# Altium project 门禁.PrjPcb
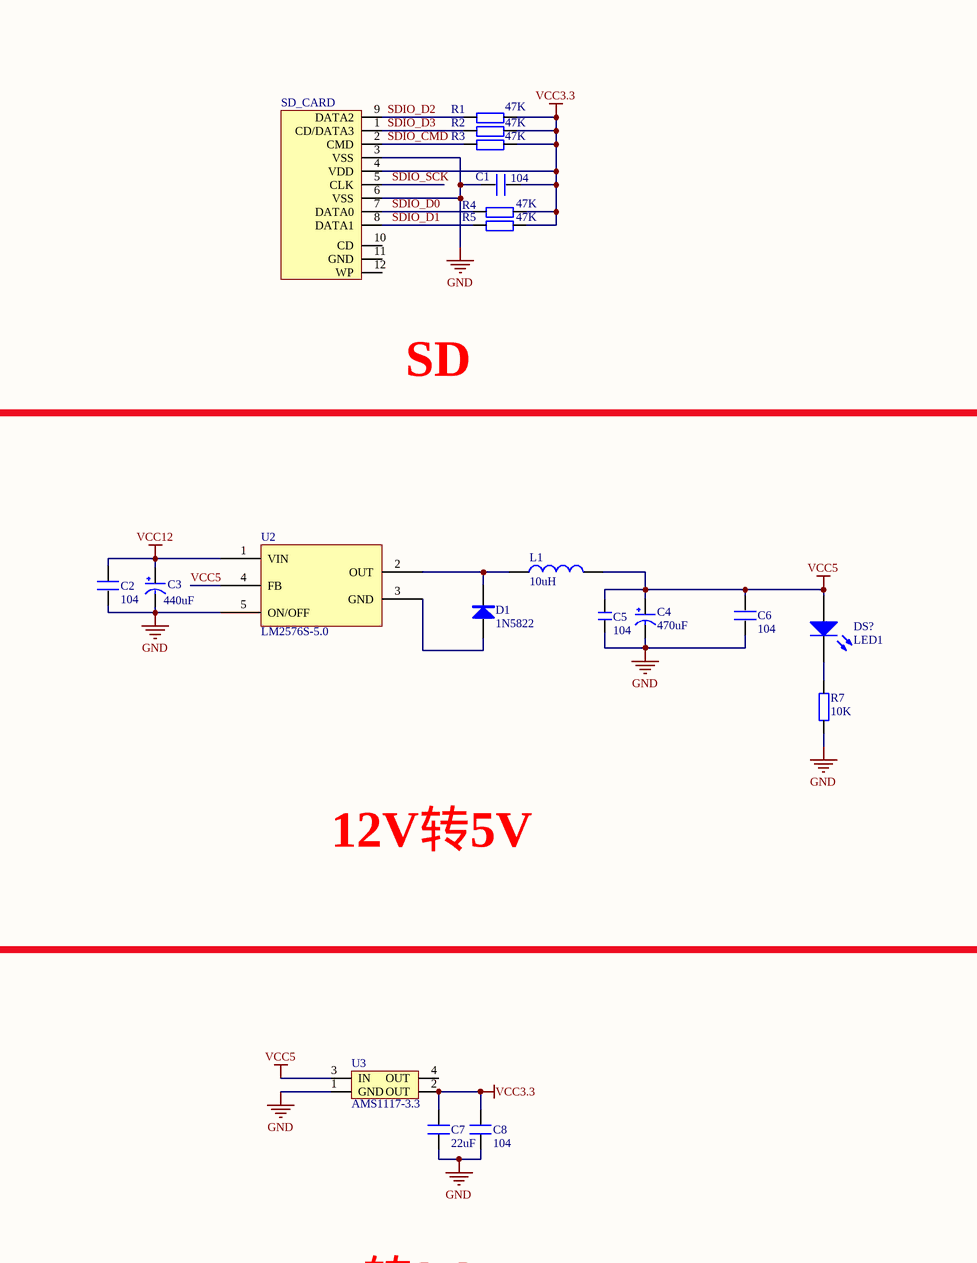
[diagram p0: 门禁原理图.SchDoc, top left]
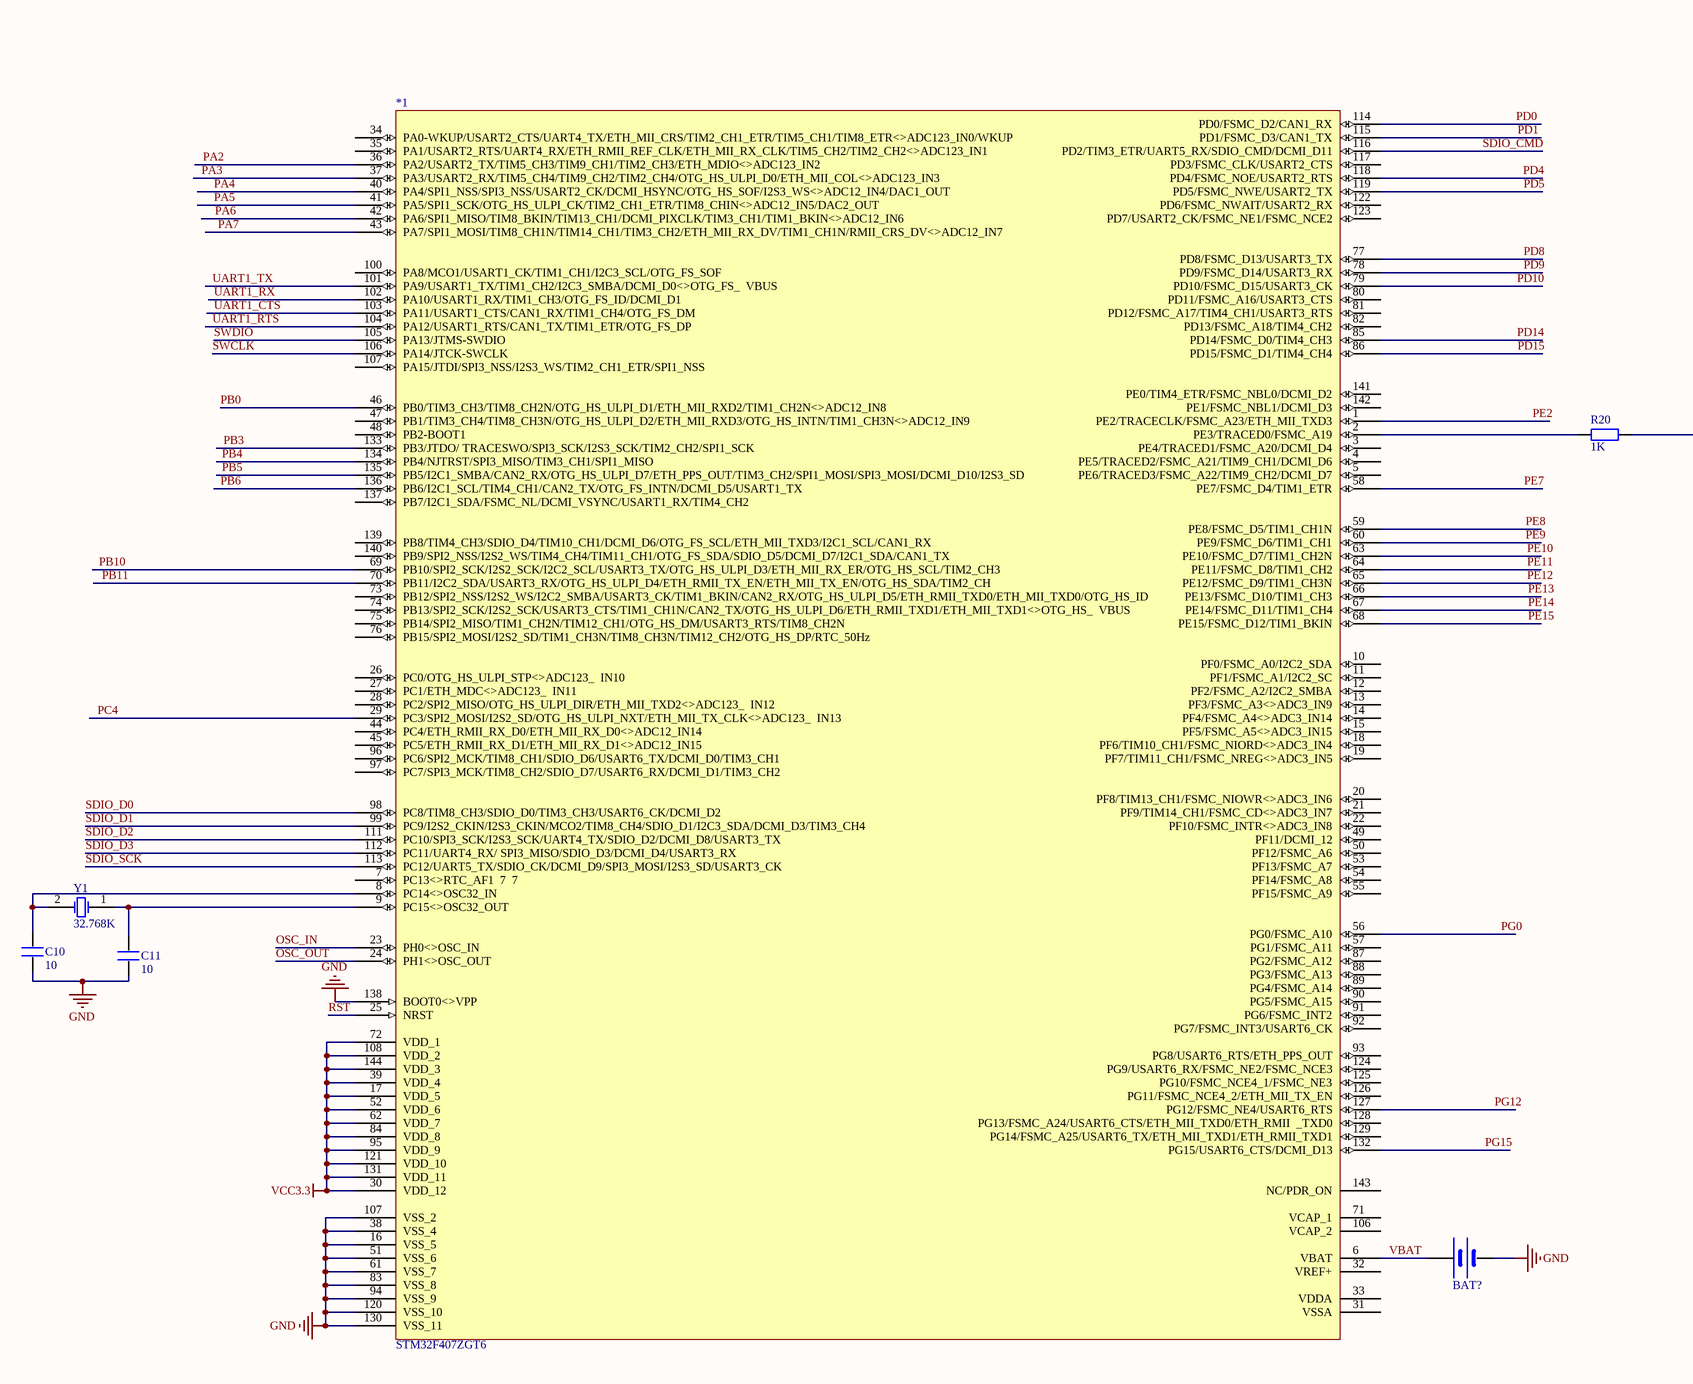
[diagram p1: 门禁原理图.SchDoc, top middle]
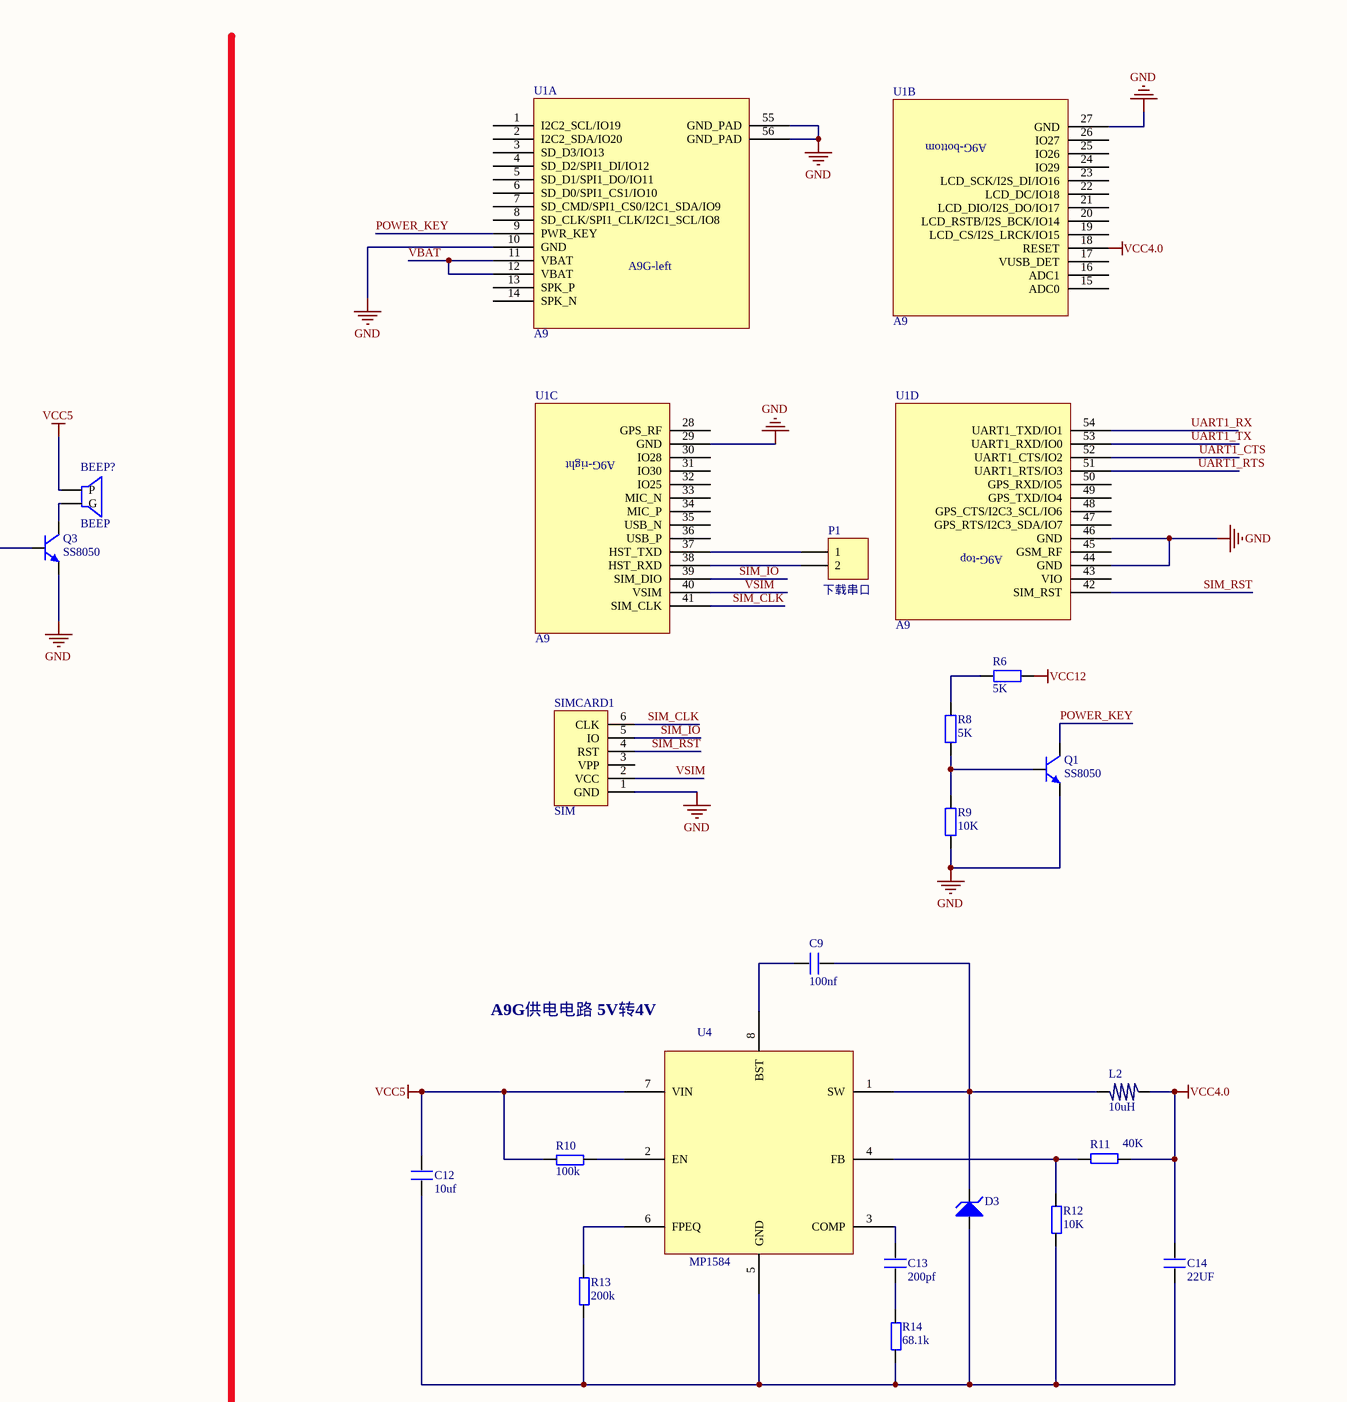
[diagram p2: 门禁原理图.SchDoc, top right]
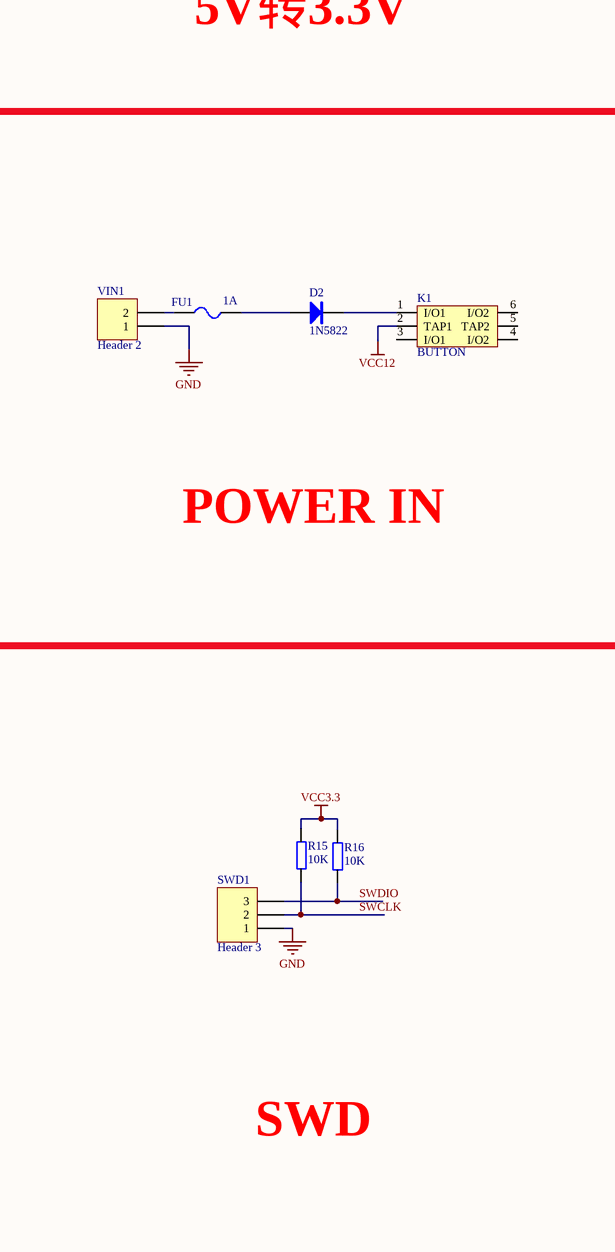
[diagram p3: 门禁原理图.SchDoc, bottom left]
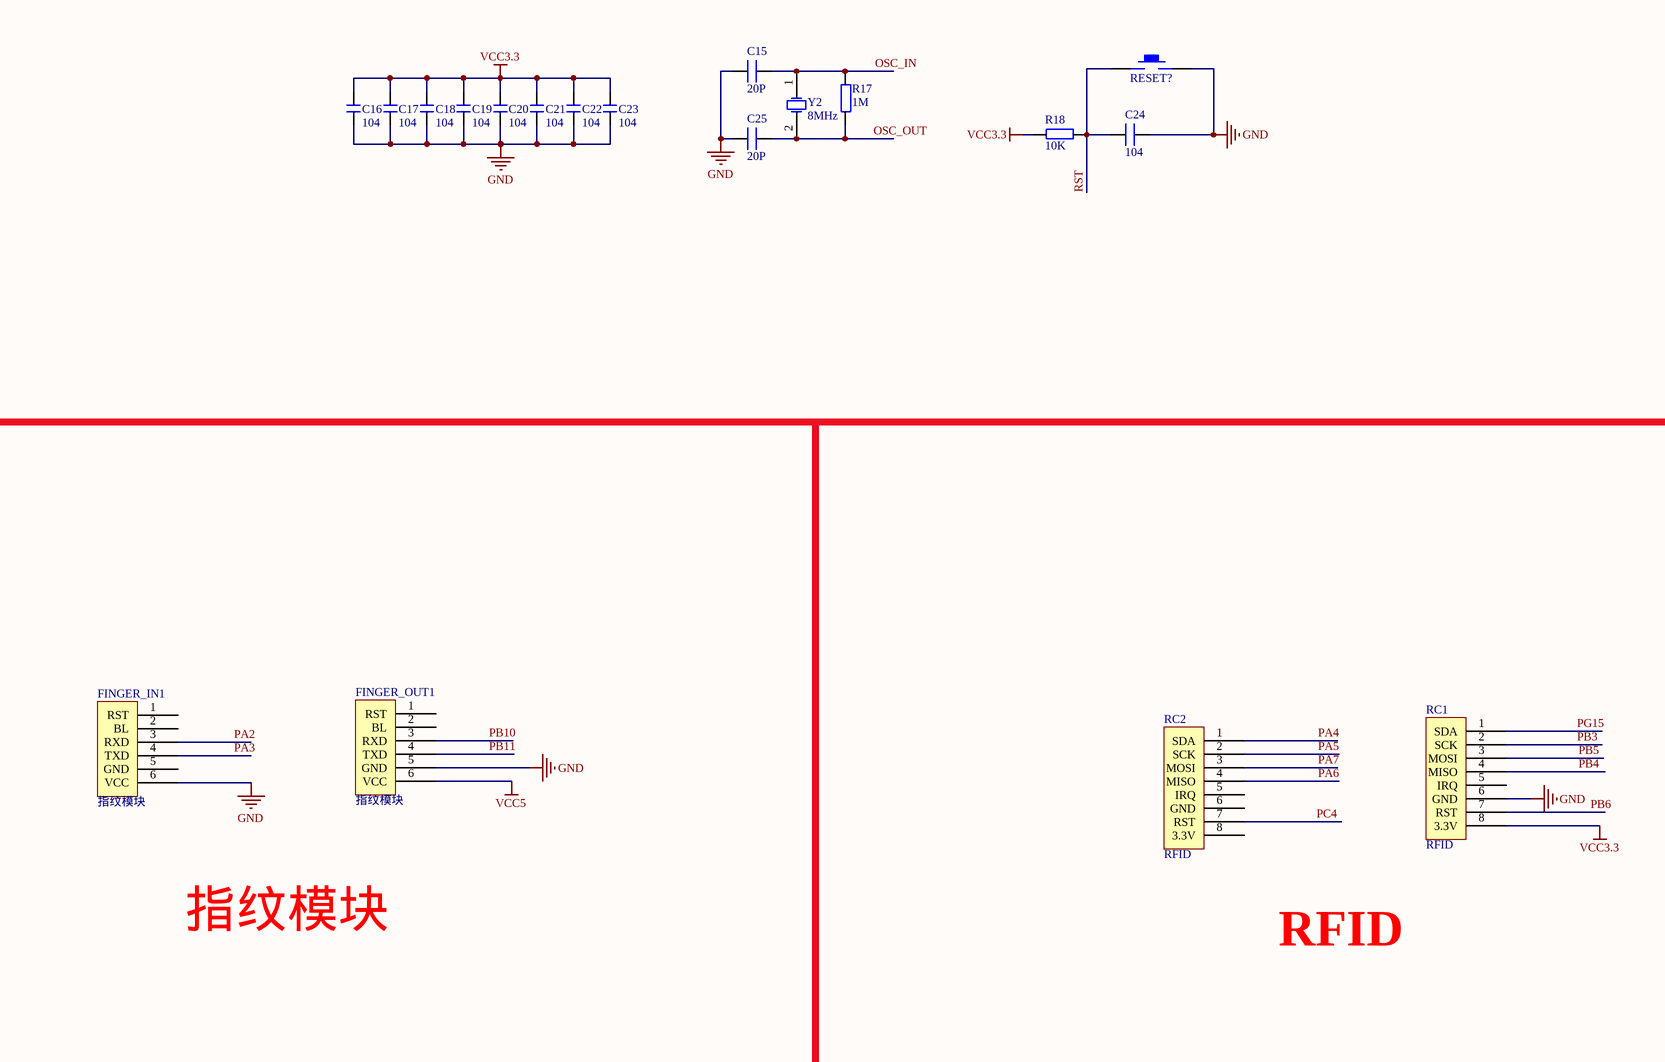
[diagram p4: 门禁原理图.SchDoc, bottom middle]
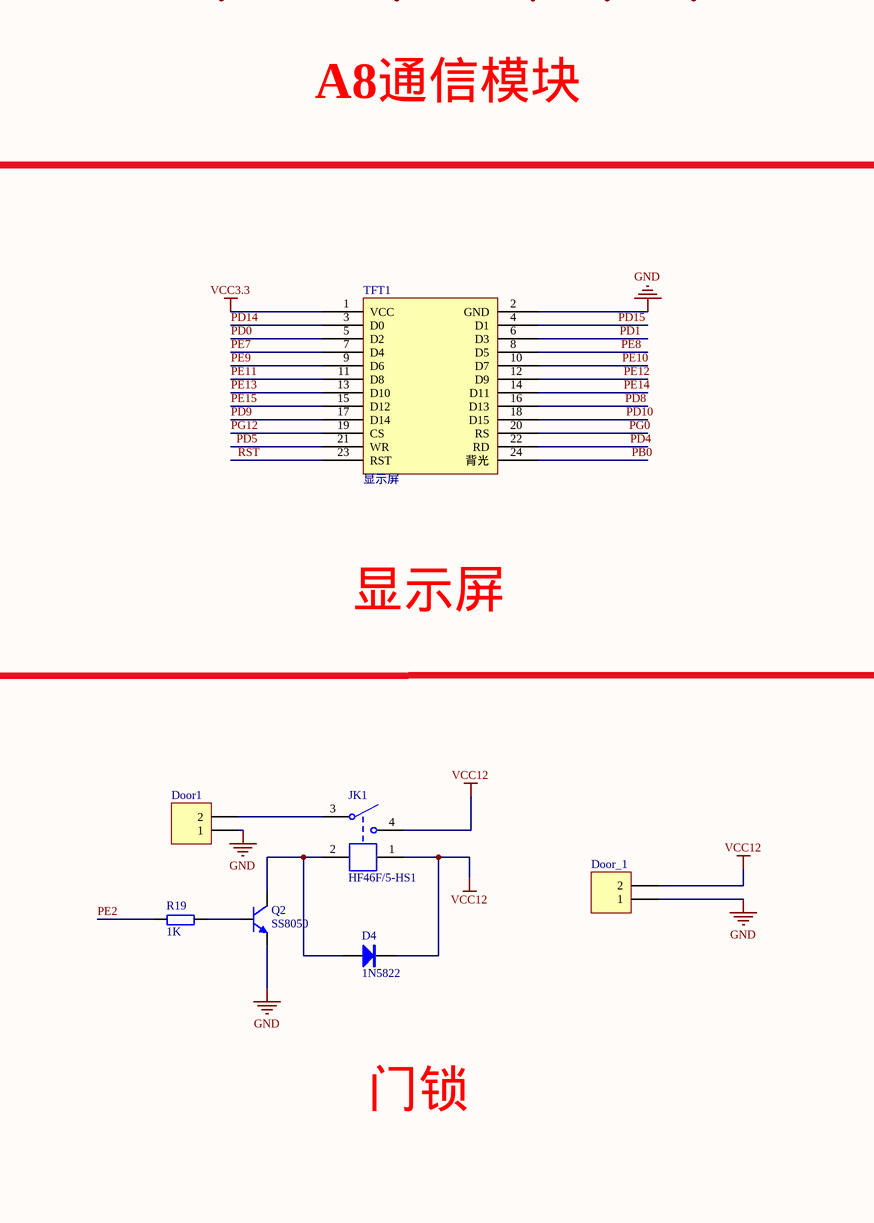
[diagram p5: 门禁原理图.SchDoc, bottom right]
1 sheet, 80 parts. Net scope: global (net labels, ports and power ports of the same name join across sheets).

## Sheet 门禁原理图.SchDoc
size D

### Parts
*1  STM32F407ZGT6
BAT?  BATT  [BATM]  (value not drawn)
BEEP?  BEEP  [BELL-5]
C1  104  [0603P]
C2  104  [0603P]
C3  440uF  [CC6.56.5]
C4  470uF  [CC6.56.5]
C5  104  [C 0805_L]
C6  104  [0805]
C7  22uF  [0603P]
C8  104  [0603P]
C9  100nf  [0805]
C10  10  [0603P]
C11  10  [0603P]
C12  10uf  [0805]
C13  200pf  [0805]
C14  22UF  [0603P]
C15  20P  [0805]
C16  104  [C 0805_L]
C17  104  [C 0805_L]
C18  104  [C 0805_L]
C19  104  [C 0805_L]
C20  104  [C 0805_L]
C21  104  [C 0805_L]
C22  104  [C 0805_L]
C23  104  [C 0805_L]
C24  104  [0805]
C25  20P  [0805]
D1  1N5822  [DIODE_3*5.3]
D2  1N5822  [DIODE_3*5.3]
D3  TVS  [0603D]  (value not drawn)
D4  1N5822  [DIODE_3*5.3]
Door1  Door  [HDR1X2]  (value not drawn)
Door_1  Header 2  [HDR1X2]  (value not drawn)
DS?  LED1  [SMDLED]
FINGER_IN1  指纹模块  [HDR2.54-LI-6P]
FINGER_OUT1  指纹模块  [HDR2.54-LI-6P]
FU1  1A  [FU 1812]
JK1  HF46F/5-HS1  [HF46-xx-HS1]
K1  BUTTON  [BTN8.5*8.5]
L1  10uH  [L 0805]
L2  10uH  [0805]
P1  下载串口  [HDR1X2]
Q1  SS8050  [SOT23-3N]
Q2  SS8050  [SOT23-3N]
Q3  SS8050  [SOT23-3N]
R1  47K  [0603P]
R2  47K  [0603P]
R3  47K  [0603P]
R4  47K  [0603P]
R5  47K  [0603P]
R6  5K  [R 0805_L]
R7  10K  [0805]
R8  5K  [R 0805_L]
R9  10K  [R 0805_L]
R10  100k  [0805]
R11  40K  [0805]
R12  10K  [0805]
R13  200k  [0805]
R14  68.1k  [0805]
R15  10K  [0805]
R16  10K  [0805]
R17  1M  [0805]
R18  10K  [0805]
R19  1K  [0805]
R20  1K  [R 0805_L]
RC1  RFID  [HDR2.54-LI-8P]
RC2  RFID  [HDR2.54-LI-8P]
RESET?  KEY_M  [KEY_M]  (value not drawn)
SD_CARD  sd card  [SDCARD_L]  (value not drawn)
SIMCARD1  SIM  [MICRO SIM]
SWD1  Header 3  [HDR1X3]
TFT1  显示屏  [HDR2.54-LI-2x12P]
U1  A9  [A9]  (parts A,B,C,D of 4)
U2  LM2576S-5.0  [TO263-5A]
U3  AMS1117-3.3  [AMS1117]
U4  MP1584  [SOP8_L]
VIN1  Header 2  [HDR1X2]
Y1  32.768K  [XTAL32]
Y2  8MHz  [XTAL_US]

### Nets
GND: *1.16(VSS_5) *1.38(VSS_4) *1.51(VSS_6) *1.61(VSS_7) *1.83(VSS_8) *1.94(VSS_9) *1.107(PA15/JTDI/SPI3_NSS/I2S3_WS/TIM2_CH1_ETR/SPI1_NSS) *1.120(VSS_10) *1.130(VSS_11) *1.138(BOOT0<>VPP) BAT?.2(GND) C1.1 C2.1 C3.2(GND) C4.2(GND) C5.1 C6.1 C7.1 C8.1 C10.2 C11.1 C15.1 C16.1 C17.1 C18.1 C19.1 C20.1 C21.1 C22.1 C23.1 C24.1 C25.1 Door1.1 Door_1.1 FINGER_IN1.6(VCC) FINGER_OUT1.5(GND) Q1.2(E) Q2.2(E) Q3.2(E) R7.1 R9.1 RC1.6(GND) RESET?.2 SD_CARD.3(VSS) SD_CARD.6(VSS) SIMCARD1.1(GND) SWD1.1 TFT1.2(GND) U1.10(GND) U1.27(GND) U1.29(GND) U1.44(GND) U1.46(GND) U1.55(GND_PAD) U1.56(GND_PAD) U2.5(ON/OFF) U3.1(GND) VIN1.1
VCC3.3: *1.17(VDD_5) *1.30(VDD_12) *1.39(VDD_4) *1.52(VDD_6) *1.62(VDD_7) *1.72(VDD_1) *1.84(VDD_8) *1.95(VDD_9) *1.108(VDD_2) *1.121(VDD_10) *1.131(VDD_11) *1.144(VDD_3) C1.2 C7.2 C8.2 C16.2 C17.2 C18.2 C19.2 C20.2 C21.2 C22.2 C23.2 R1.2 R2.2 R3.2 R4.2 R5.2 R15.2 R16.2 R18.2 RC1.8(3.3V) SD_CARD.4(VDD) TFT1.1(VCC) U3.2(OUT)
VCC4.0: C14.2 L2.1 R11.1 U1.18(RESET)
VCC5: BEEP?.1(P) C4.1(VCC) C5.2 C6.2 C12.2 DS?.1(A) FINGER_OUT1.6(VCC) L1.2 R10.1 U2.4(FB) U3.3(IN) U4.7(VIN)
VCC12: C2.2 C3.1(VCC) D4.2(K) Door_1.2 JK1.1 JK1.4 K1.2(TAP1) R6.1 U2.1(VIN)
OSC_IN: *1.23(PH0<>OSC_IN) C15.2 R17.2 Y2.1(OSC1)
OSC_OUT: *1.24(PH1<>OSC_OUT) C25.2 R17.1 Y2.2(OSC2)
PA2: *1.36(PA2/USART2_TX/TIM5_CH3/TIM9_CH1/TIM2_CH3/ETH_MDIO<>ADC123_IN2) FINGER_IN1.3(RXD)
PA3: *1.37(PA3/USART2_RX/TIM5_CH4/TIM9_CH2/TIM2_CH4/OTG_HS_ULPI_D0/ETH_MII_COL<>ADC123_IN3) FINGER_IN1.4(TXD)
PA4: *1.40(PA4/SPI1_NSS/SPI3_NSS/USART2_CK/DCMI_HSYNC/OTG_HS_SOF/I2S3_WS<>ADC12_IN4/DAC1_OUT) RC2.1(SDA)
PA5: *1.41(PA5/SPI1_SCK/OTG_HS_ULPI_CK/TIM2_CH1_ETR/TIM8_CHIN<>ADC12_IN5/DAC2_OUT) RC2.2(SCK)
PA6: *1.42(PA6/SPI1_MISO/TIM8_BKIN/TIM13_CH1/DCMI_PIXCLK/TIM3_CH1/TIM1_BKIN<>ADC12_IN6) RC2.4(MISO)
PA7: *1.43(PA7/SPI1_MOSI/TIM8_CH1N/TIM14_CH1/TIM3_CH2/ETH_MII_RX_DV/TIM1_CH1N/RMII_CRS_DV<>ADC12_IN7) RC2.3(MOSI)
PB0: *1.46(PB0/TIM3_CH3/TIM8_CH2N/OTG_HS_ULPI_D1/ETH_MII_RXD2/TIM1_CH2N<>ADC12_IN8) TFT1.24(背光)
PB3: *1.133(PB3/JTDO/_TRACESWO/SPI3_SCK/I2S3_SCK/TIM2_CH2/SPI1_SCK) RC1.2(SCK)
PB4: *1.134(PB4/NJTRST/SPI3_MISO/TIM3_CH1/SPI1_MISO) RC1.4(MISO)
PB5: *1.135(PB5/I2C1_SMBA/CAN2_RX/OTG_HS_ULPI_D7/ETH_PPS_OUT/TIM3_CH2/SPI1_MOSI/SPI3_MOSI/DCMI_D10/I2S3_SD) RC1.3(MOSI)
PB6: *1.136(PB6/I2C1_SCL/TIM4_CH1/CAN2_TX/OTG_FS_INTN/DCMI_D5/USART1_TX) RC1.7(RST)
PB10: *1.69(PB10/SPI2_SCK/I2S2_SCK/I2C2_SCL/USART3_TX/OTG_HS_ULPI_D3/ETH_MII_RX_ER/OTG_HS_SCL/TIM2_CH3) FINGER_OUT1.3(RXD)
PB11: *1.70(PB11/I2C2_SDA/USART3_RX/OTG_HS_ULPI_D4/ETH_RMII_TX_EN/ETH_MII_TX_EN/OTG_HS_SDA/TIM2_CH) FINGER_OUT1.4(TXD)
PC4: *1.29(PC3/SPI2_MOSI/I2S2_SD/OTG_HS_ULPI_NXT/ETH_MII_TX_CLK<>ADC123___IN13) RC2.7(RST)
PD0: *1.114(PD0/FSMC_D2/CAN1_RX) TFT1.5(D2)
PD1: *1.115(PD1/FSMC_D3/CAN1_TX) TFT1.6(D3)
PD4: *1.118(PD4/FSMC_NOE/USART2_RTS) TFT1.22(RD)
PD5: *1.119(PD5/FSMC_NWE/USART2_TX) TFT1.21(WR)
PD8: *1.77(PD8/FSMC_D13/USART3_TX) TFT1.16(D13)
PD9: *1.78(PD9/FSMC_D14/USART3_RX) TFT1.17(D14)
PD10: *1.79(PD10/FSMC_D15/USART3_CK) TFT1.18(D15)
PD14: *1.85(PD14/FSMC_D0/TIM4_CH3) TFT1.3(D0)
PD15: *1.86(PD15/FSMC_D1/TIM4_CH4) TFT1.4(D1)
PE2: *1.1(PE2/TRACECLK/FSMC_A23/ETH_MII_TXD3) R19.1
PE7: *1.58(PE7/FSMC_D4/TIM1_ETR) TFT1.7(D4)
PE8: *1.59(PE8/FSMC_D5/TIM1_CH1N) TFT1.8(D5)
PE9: *1.60(PE9/FSMC_D6/TIM1_CH1) TFT1.9(D6)
PE10: *1.63(PE10/FSMC_D7/TIM1_CH2N) TFT1.10(D7)
PE11: *1.64(PE11/FSMC_D8/TIM1_CH2) TFT1.11(D8)
PE12: *1.65(PE12/FSMC_D9/TIM1_CH3N) TFT1.12(D9)
PE13: *1.66(PE13/FSMC_D10/TIM1_CH3) TFT1.13(D10)
PE14: *1.67(PE14/FSMC_D11/TIM1_CH4) TFT1.14(D11)
PE15: *1.68(PE15/FSMC_D12/TIM1_BKIN) TFT1.15(D12)
PG0: *1.56(PG0/FSMC_A10) TFT1.20(RS)
PG12: *1.127(PG12/FSMC_NE4/USART6_RTS) TFT1.19(CS)
PG15: *1.132(PG15/USART6_CTS/DCMI_D13) RC1.1(SDA)
POWER_KEY: Q1.3(C) U1.9(PWR_KEY)
RST: *1.25(NRST) C24.2 R18.1 RESET?.1 TFT1.23(RST)
SDIO_CMD: *1.116(PD2/TIM3_ETR/UART5_RX/SDIO_CMD/DCMI_D11) R3.1 SD_CARD.2(CMD)
SDIO_D0: *1.98(PC8/TIM8_CH3/SDIO_D0/TIM3_CH3/USART6_CK/DCMI_D2) R4.1 SD_CARD.7(DATA0)
SDIO_D1: *1.99(PC9/I2S2_CKIN/I2S3_CKIN/MCO2/TIM8_CH4/SDIO_D1/I2C3_SDA/DCMI_D3/TIM3_CH4) R5.1 SD_CARD.8(DATA1)
SDIO_D2: *1.111(PC10/SPI3_SCK/I2S3_SCK/UART4_TX/SDIO_D2/DCMI_D8/USART3_TX) R1.1 SD_CARD.9(DATA2)
SDIO_D3: *1.112(PC11/UART4_RX/_SPI3_MISO/SDIO_D3/DCMI_D4/USART3_RX) R2.1 SD_CARD.1(CD/DATA3)
SDIO_SCK: *1.113(PC12/UART5_TX/SDIO_CK/DCMI_D9/SPI3_MOSI/I2S3_SD/USART3_CK) SD_CARD.5(CLK)
SIM_CLK: SIMCARD1.6(CLK) U1.41(SIM_CLK)
SIM_IO: SIMCARD1.5(IO) U1.39(SIM_DIO)
SIM_RST: SIMCARD1.4(RST) U1.42(SIM_RST)
SWCLK: *1.106(PA14/JTCK-SWCLK) R15.1 SWD1.2
SWDIO: *1.105(PA13/JTMS-SWDIO) R16.1 SWD1.3
UART1_CTS: *1.103(PA11/USART1_CTS/CAN1_RX/TIM1_CH4/OTG_FS_DM) U1.52(UART1_CTS/IO2)
UART1_RTS: *1.104(PA12/USART1_RTS/CAN1_TX/TIM1_ETR/OTG_FS_DP) U1.51(UART1_RTS/IO3)
UART1_RX: *1.102(PA10/USART1_RX/TIM1_CH3/OTG_FS_ID/DCMI_D1) U1.54(UART1_TXD/IO1)
UART1_TX: *1.101(PA9/USART1_TX/TIM1_CH2/I2C3_SMBA/DCMI_D0<>OTG_FS___VBUS) U1.53(UART1_RXD/IO0)
VBAT: *1.6(VBAT) BAT?.1(VCC) U1.11(VBAT) U1.12(VBAT)
VSIM: SIMCARD1.2(VCC) U1.40(VSIM)
Net*1_2: *1.2(PE3/TRACED0/FSMC_A19) R20.1
Net*1_8: *1.8(PC14<>OSC32_IN) C10.1 Y1.2(OSC2)
Net*1_9: *1.9(PC15<>OSC32_OUT) C11.2 Y1.1(OSC1)
NetBEEP?_2: BEEP?.2(G) Q3.3(C)
NetC9_1: C9.1 U4.8(BST)
NetC9_2: C9.2 D3.K L2.2 U4.1(SW)
NetC12_1: C12.1 C14.1 D3.A R12.1 R13.1 R14.1 U4.5(GND)
NetC13_1: C13.1 R14.2
NetC13_2: C13.2 U4.3(COMP)
NetD1_1: D1.1(A) U2.3(GND)
NetD1_2: D1.2(K) L1.1 U2.2(OUT)
NetD2_1: D2.1(A) FU1.2
NetD2_2: D2.2(K) K1.1(I/O1)
NetD4_1: D4.1(A) JK1.2 Q2.3(C)
NetDoor1_2: Door1.2 JK1.3
NetDS?_2: DS?.2(K) R7.2
NetFU1_1: FU1.1 VIN1.2
NetP1_1: P1.1 U1.37(HST_TXD)
NetP1_2: P1.2 U1.38(HST_RXD)
NetQ1_1: Q1.1(B) R8.1 R9.2
NetQ2_1: Q2.1(B) R19.2
NetQ3_1: Q3.1(B) R20.2
NetR6_2: R6.2 R8.2
NetR10_2: R10.2 U4.2(EN)
NetR11_2: R11.2 R12.2 U4.4(FB)
NetR13_2: R13.2 U4.6(FPEQ)

Not connected (* = marked no-connect by the designer): *1 3(PE4/TRACED1/FSMC_A20/DCMI_D4) 4(PE5/TRACED2/FSMC_A21/TIM9_CH1/DCMI_D6) 5(PE6/TRACED3/FSMC_A22/TIM9_CH2/DCMI_D7) 7(PC13<>RTC_AF1__7__7) 10(PF0/FSMC_A0/I2C2_SDA) 11(PF1/FSMC_A1/I2C2_SC) 12(PF2/FSMC_A2/I2C2_SMBA) 13(PF3/FSMC_A3<>ADC3_IN9) 14(PF4/FSMC_A4<>ADC3_IN14) 15(PF5/FSMC_A5<>ADC3_IN15) 18(PF6/TIM10_CH1/FSMC_NIORD<>ADC3_IN4) 19(PF7/TIM11_CH1/FSMC_NREG<>ADC3_IN5) 20(PF8/TIM13_CH1/FSMC_NIOWR<>ADC3_IN6) 21(PF9/TIM14_CH1/FSMC_CD<>ADC3_IN7) 22(PF10/FSMC_INTR<>ADC3_IN8) 26(PC0/OTG_HS_ULPI_STP<>ADC123___IN10) 27(PC1/ETH_MDC<>ADC123___IN11) 28(PC2/SPI2_MISO/OTG_HS_ULPI_DIR/ETH_MII_TXD2<>ADC123___IN12) 31(VSSA) 32(VREF+) 33(VDDA) 34(PA0-WKUP/USART2_CTS/UART4_TX/ETH_MII_CRS/TIM2_CH1_ETR/TIM5_CH1/TIM8_ETR<>ADC123_IN0/WKUP) 35(PA1/USART2_RTS/UART4_RX/ETH_RMII_REF_CLK/ETH_MII_RX_CLK/TIM5_CH2/TIM2_CH2<>ADC123_IN1) 44(PC4/ETH_RMII_RX_D0/ETH_MII_RX_D0<>ADC12_IN14) 45(PC5/ETH_RMII_RX_D1/ETH_MII_RX_D1<>ADC12_IN15) 47(PB1/TIM3_CH4/TIM8_CH3N/OTG_HS_ULPI_D2/ETH_MII_RXD3/OTG_HS_INTN/TIM1_CH3N<>ADC12_IN9) 48(PB2-BOOT1) 49(PF11/DCMI_12) 50(PF12/FSMC_A6) 53(PF13/FSMC_A7) 54(PF14/FSMC_A8) 55(PF15/FSMC_A9) 57(PG1/FSMC_A11) 71(VCAP_1) 73(PB12/SPI2_NSS/I2S2_WS/I2C2_SMBA/USART3_CK/TIM1_BKIN/CAN2_RX/OTG_HS_ULPI_D5/ETH_RMII_TXD0/ETH_MII_TXD0/OTG_HS_ID) 74(PB13/SPI2_SCK/I2S2_SCK/USART3_CTS/TIM1_CH1N/CAN2_TX/OTG_HS_ULPI_D6/ETH_RMII_TXD1/ETH_MII_TXD1<>OTG_HS___VBUS) 75(PB14/SPI2_MISO/TIM1_CH2N/TIM12_CH1/OTG_HS_DM/USART3_RTS/TIM8_CH2N) 76(PB15/SPI2_MOSI/I2S2_SD/TIM1_CH3N/TIM8_CH3N/TIM12_CH2/OTG_HS_DP/RTC_50Hz) 80(PD11/FSMC_A16/USART3_CTS) 81(PD12/FSMC_A17/TIM4_CH1/USART3_RTS) 82(PD13/FSMC_A18/TIM4_CH2) 87(PG2/FSMC_A12) 88(PG3/FSMC_A13) 89(PG4/FSMC_A14) 90(PG5/FSMC_A15) 91(PG6/FSMC_INT2) 92(PG7/FSMC_INT3/USART6_CK) 93(PG8/USART6_RTS/ETH_PPS_OUT) 96(PC6/SPI2_MCK/TIM8_CH1/SDIO_D6/USART6_TX/DCMI_D0/TIM3_CH1) 97(PC7/SPI3_MCK/TIM8_CH2/SDIO_D7/USART6_RX/DCMI_D1/TIM3_CH2) 100(PA8/MCO1/USART1_CK/TIM1_CH1/I2C3_SCL/OTG_FS_SOF) 117(PD3/FSMC_CLK/USART2_CTS) 122(PD6/FSMC_NWAIT/USART2_RX) 123(PD7/USART2_CK/FSMC_NE1/FSMC_NCE2) 124(PG9/USART6_RX/FSMC_NE2/FSMC_NCE3) 125(PG10/FSMC_NCE4_1/FSMC_NE3) 126(PG11/FSMC_NCE4_2/ETH_MII_TX_EN) 128(PG13/FSMC_A24/USART6_CTS/ETH_MII_TXD0/ETH_RMII___TXD0) 129(PG14/FSMC_A25/USART6_TX/ETH_MII_TXD1/ETH_RMII_TXD1) 137(PB7/I2C1_SDA/FSMC_NL/DCMI_VSYNC/USART1_RX/TIM4_CH2) 139(PB8/TIM4_CH3/SDIO_D4/TIM10_CH1/DCMI_D6/OTG_FS_SCL/ETH_MII_TXD3/I2C1_SCL/CAN1_RX) 140(PB9/SPI2_NSS/I2S2_WS/TIM4_CH4/TIM11_CH1/OTG_FS_SDA/SDIO_D5/DCMI_D7/I2C1_SDA/CAN1_TX) 141(PE0/TIM4_ETR/FSMC_NBL0/DCMI_D2) 142(PE1/FSMC_NBL1/DCMI_D3) 143(NC/PDR_ON); FINGER_IN1 1(RST) 2(BL) 5(GND); FINGER_OUT1 1(RST) 2(BL); K1 3(I/O1) 4(I/O2) 5(TAP2) 6(I/O2); RC1 5(IRQ); RC2 5(IRQ) 6(GND) 8(3.3V); SD_CARD 10(CD) 11(GND) 12(WP); SIMCARD1 3(VPP); U1 1(I2C2_SCL/IO19) 2(I2C2_SDA/IO20) 3(SD_D3/IO13) 4(SD_D2/SPI1_DI/IO12) 5(SD_D1/SPI1_DO/IO11) 6(SD_D0/SPI1_CS1/IO10) 7(SD_CMD/SPI1_CS0/I2C1_SDA/IO9) 8(SD_CLK/SPI1_CLK/I2C1_SCL/IO8) 13(SPK_P) 14(SPK_N) 15(ADC0) 16(ADC1) 17(VUSB_DET) 19(LCD_CS/I2S_LRCK/IO15) 20(LCD_RSTB/I2S_BCK/IO14) 21(LCD_DIO/I2S_DO/IO17) 22(LCD_DC/IO18) 23(LCD_SCK/I2S_DI/IO16) 24(IO29) 25(IO26) 26(IO27) 28(GPS_RF) 30(IO28) 31(IO30) 32(IO25) 33(MIC_N) 34(MIC_P) 35(USB_N) 36(USB_P) 43(VIO) 45(GSM_RF) 47(GPS_RTS/I2C3_SDA/IO7) 48(GPS_CTS/I2C3_SCL/IO6) 49(GPS_TXD/IO4) 50(GPS_RXD/IO5); U3 4(OUT)

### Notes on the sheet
- SD
- 12V转5V
- A9G供电电路 5V转4V
- 5V转3.3V
- A8通信模块
- POWER IN
- 显示屏
- 指纹模块
- RFID
- SWD
- 门锁

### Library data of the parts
BAT? = BAT
C1 C2 C6-C9 C12-C14 = C
C3 C4 = CAP
C5 C16-C23 = C: 无极性贴片电容; 版权归属: 源创客
C10 C11 = C_2
C15 C25 = C_3
C24 = C_1
D1 D2 D4 = 1N4148: 高速开关二极管; 版权归属: 源创客
D3 = D-MANOSTAT: manostat diode
Door1 Door_1 P1 VIN1 = Header 2: Header, 2-Pin
DS? = LED2: Typical RED, GREEN, YELLOW, AMBER GaAs LED
FU1 = FU: 贴片保险丝; 版权归属: 源创客
JK1 = HF46F/5-HS1: 5V一组常开; BOM名称: 5V继电器; 版权归属: 源创客
L1 = L: 小功率贴片电感; 版权归属: 源创客
L2 = L
Q1-Q3 = 8050-SMD: 高频放大-NPN型; 版权归属: 源创客; 属性: 40V 1.5A 1W 100MHZ
R1-R5 R7 R10-R16 R18 R19 = R
R6 R8 R9 R20 = R: 贴片电阻; 版权归属: 源创客
R17 = R_2
RC1 RC2 = RC522
SIMCARD1 = MICRO SIM: SIM卡座; 版权归属: 源创客
SWD1 = Header 3: Header, 3-Pin
TFT1 = TFFT显示屏
U2 = Component_1
U3 = AMS1117
U4 = MP1854
Y1 = XTAL_1: Crystal Oscillator
Y2 = XTAL: Crystal Oscillator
